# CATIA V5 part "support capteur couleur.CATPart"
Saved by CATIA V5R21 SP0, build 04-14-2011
Part number: couleur
Bounding box of the stored display mesh (mm): x 0 to 32, y 0 to 24, z 0 to 8
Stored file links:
  C:\Users\2027.DESARCY-LEMIE30\Desktop\Assemblage26.05\support capteur couleur.CATPart
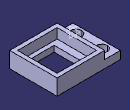
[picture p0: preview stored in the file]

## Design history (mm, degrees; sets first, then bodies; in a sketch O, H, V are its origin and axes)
Body1 (main body)
  Sketch1 on xy-plane, origin (0, 0, 0), H (1, 0, 0), V (0, 1, 0)
    line L1 (0, 0) -> (32, 0)
    line L2 (32, 0) -> (32, 24)
    line L3 (32, 24) -> (0, 24)
    line L4 (0, 24) -> (0, 0)
    length L2 = 24
    length L3 = 32
    horizontal: L1 H, L3 H
    vertical: L2 V, L4 V
  Pad1: profile Sketch1, direction (0, 0, 1), length 4
  Sketch2 on end face of Pad1, origin (0, 0, 4), H (1, 0, 0), V (0, 1, 0)
    line L1 (8, 24) -> (32, 24)
    line L2 (32, 24) -> (32, 0)
    line L3 (32, 0) -> (8, 0)
    line L4 (8, 0) -> (8, 24)
    reference projected line E1 (32, 24) -> (0, 24) from edge [face of Pad1 from Sketch1.L3 | end face of Pad1]
    reference projected line E2 (0, 24) -> (0, 0) from edge [face of Pad1 from Sketch1.L4 | end face of Pad1]
    reference projected line E3 (32, 0) -> (32, 24) from edge [face of Pad1 from Sketch1.L2 | end face of Pad1]
    distance H L3 = 0
    distance L1 E1 = 0
    distance L4 E2 = 8
    distance L2 E3 = 0
    horizontal: L1 H, L3 H
    vertical: L2 V, L4 V
  Pad2: profile Sketch2, direction (0, 0, 1), length 4
  Sketch3 on end face of Pad2, origin (0, 0, 8), H (1, 0, 0), V (0, 1, 0)
    line L1 (10, 22) -> (30, 22)
    line L2 (30, 22) -> (30, 2)
    line L3 (30, 2) -> (10, 2)
    line L4 (10, 2) -> (10, 22)
    reference projected line E1 (32, 24) -> (8, 24) from edge [face of Pad2 | end face of Pad2]
    reference projected line E2 (32, 0) -> (32, 24) from edge [face of Pad2 | end face of Pad2]
    reference projected line E3 (8, 0) -> (32, 0) from edge [face of Pad2 | end face of Pad2]
    reference projected line E4 (8, 24) -> (8, 0) from edge [face of Pad2 from Sketch2.L4 | end face of Pad2]
    distance L1 E1 = 2
    distance L2 E2 = 2
    distance L3 E3 = 2
    distance L4 E4 = 2
    horizontal: L1 H, L3 H
    vertical: L2 V, L4 V
  Pocket1: profile Sketch3, direction (0, 0, -1), length 5
  Sketch4 on end face of Pocket1, origin (0, 0, 3), H (1, 0, 0), V (0, 1, 0)
    line L1 (13.5, 17) -> (27.4, 17)
    line L2 (27.4, 17) -> (27.4, 4)
    line L3 (27.4, 4) -> (13.5, 4)
    line L4 (13.5, 4) -> (13.5, 17)
    reference projected line E1 (10, 2) -> (30, 2) from edge [end face of Pad2 | face of Pocket1 from Sketch3.L3]
    reference projected line E2 (10, 22) -> (10, 2) from edge [end face of Pad2 | face of Pocket1 from Sketch3.L4]
    reference projected line E3 (30, 2) -> (30, 22) from edge [end face of Pad2 | face of Pocket1 from Sketch3.L2]
    reference projected line E4 (30, 22) -> (10, 22) from edge [end face of Pad2 | face of Pocket1 from Sketch3.L1]
    circle A1 centre (27.5, 19.5) radius 1.5
    circle A2 centre (12.5, 19.5) radius 1.5
    distance L3 E1 = 2
    distance L4 E2 = 3.5
    distance L2 E3 = 2.6
    distance L1 E4 = 5
    radius A1 = 1.5
    radius A2 = 1.5
    horizontal: L1 H, L3 H
    vertical: L2 V, L4 V
  Pocket2: profile Sketch4, direction (0, 0, -1), length 5
  Sketch5 on end face of Pad1, origin (0, 0, 4), H (1, 0, 0), V (0, 1, 0)
    circle A1 centre (3.85, 18.5) radius 2.85
    circle A2 centre (3.85, 5.5) radius 2.85
    radius A1 = 2.85
  Pocket3: profile Sketch5, direction (0, 0, -1), length 5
